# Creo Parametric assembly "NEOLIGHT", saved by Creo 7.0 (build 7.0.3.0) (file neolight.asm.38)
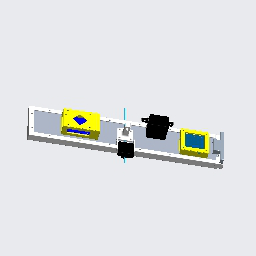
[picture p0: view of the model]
Units: millimeter Kilogram Sec (mmKs); MM, KILOGRAM, SECS

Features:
  1. datum plane "ASM_RIGHT"
  2. datum plane "ASM_TOP"
  3. datum plane "ASM_FRONT"
  4. coordinate system
  5. component "ALUMINIUM_BOARD"
  6. component "EDGE_COVER_0"
  7. component "EDGE_COVER_0"
  8. component "EDGE_COVER_0"
  9. component "EDGE_COVER_0"
  10. component "EDGE_COVER_0"
  11. component "EDGE_COVER_0"
  12. component "EDGE_COVER_1"
  13. component "EDGE_COVER_2"
  14. component "WLED_MODULE"
  15. component "ORANGEPI5PRO_MODULE"
  16. component "SET"
  17. component "DIFFUSION_PLATE"
  18. pattern "Pattern 1"
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
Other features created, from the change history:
  component "LED_STRIP" (10 times)
  component "LED_STRIP.PRT" (52 times)
  pattern "Pattern 1" (5 times)
  component "SPEAKER_MODULE"
  component "CAMERA_MODULE"
  component "WIRE_COVER"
